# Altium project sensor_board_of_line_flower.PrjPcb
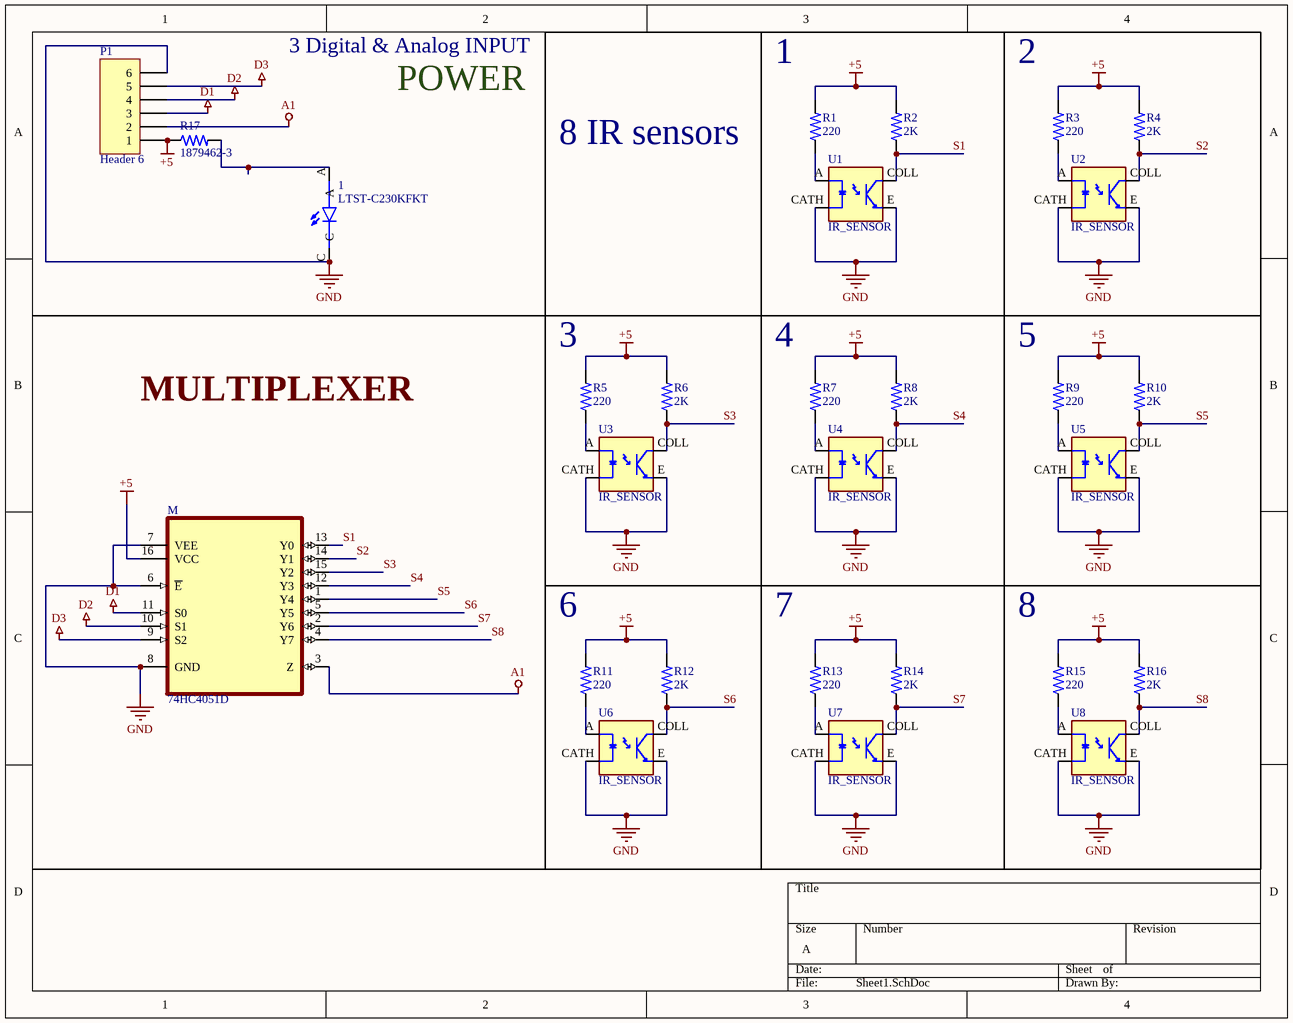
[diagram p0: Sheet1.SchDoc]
1 sheet, 28 parts. Net scope: global (net labels, ports and power ports of the same name join across sheets).
Board files: PCB1.PcbDoc, PCB2.PcbDoc, PCB3.PcbDoc

## Sheet Sheet1.SchDoc
size A; SheetNumber: 1; SheetTotal: 1

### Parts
1  LTST-C230KFKT  [LEDC3216X110]
M  74HC4051D  [SOIC127P600X175-16N]
P1  Header 6  [HDR1X6]
R1  220  [RESC3115X65N]
R2  2K  [RESC3115X65N]
R3  220  [RESC3115X65N]
R4  2K  [RESC3115X65N]
R5  220  [RESC3115X65N]
R6  2K  [RESC3115X65N]
R7  220  [RESC3115X65N]
R8  2K  [RESC3115X65N]
R9  220  [RESC3115X65N]
R10  2K  [RESC3115X65N]
R11  220  [RESC3115X65N]
R12  2K  [RESC3115X65N]
R13  220  [RESC3115X65N]
R14  2K  [RESC3115X65N]
R15  220  [RESC3115X65N]
R16  2K  [RESC3115X65N]
R17  1879462-3  [RESC3115X65N]
U1  IR_SENSOR  [OPTO_TCRT5000]
U2  IR_SENSOR  [OPTO_TCRT5000]
U3  IR_SENSOR  [OPTO_TCRT5000]
U4  IR_SENSOR  [OPTO_TCRT5000]
U5  IR_SENSOR  [OPTO_TCRT5000]
U6  IR_SENSOR  [OPTO_TCRT5000]
U7  IR_SENSOR  [OPTO_TCRT5000]
U8  IR_SENSOR  [OPTO_TCRT5000]

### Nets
+5: M.16(VCC) P1.1 R1.2 R2.2 R3.2 R4.2 R5.2 R6.2 R7.2 R8.2 R9.2 R10.2 R11.2 R12.2 R13.2 R14.2 R15.2 R16.2 R17.1
A1: M.3(Z) P1.2
D1: M.11(S0) P1.3
D2: M.10(S1) P1.4
D3: M.9(S2) P1.5
GND: 1.C M.6(~{E}) M.7(VEE) M.8(GND) P1.6 U1.CATH U1.E U2.CATH U2.E U3.CATH U3.E U4.CATH U4.E U5.CATH U5.E U6.CATH U6.E U7.CATH U7.E U8.CATH U8.E
S1: M.13(Y0) R2.1 U1.COLL
S2: M.14(Y1) R4.1 U2.COLL
S3: M.15(Y2) R6.1 U3.COLL
S4: M.12(Y3) R8.1 U4.COLL
S5: M.1(Y4) R10.1 U5.COLL
S6: M.5(Y5) R12.1 U6.COLL
S7: M.2(Y6) R14.1 U7.COLL
S8: M.4(Y7) R16.1 U8.COLL
Net1_A: 1.A R17.2
NetR1_1: R1.1 U1.A
NetR3_1: R3.1 U2.A
NetR5_1: R5.1 U3.A
NetR7_1: R7.1 U4.A
NetR9_1: R9.1 U5.A
NetR11_1: R11.1 U6.A
NetR13_1: R13.1 U7.A
NetR15_1: R15.1 U8.A

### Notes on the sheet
- 3 Digital & Analog INPUT
- POWER
- (near R1) 1
- (near R3) 2
- 8 IR sensors
- (near R5) 3
- (near R7) 4
- (near R9) 5
- MULTIPLEXER
- (near R11) 6
- (near R13) 7
- (near R15) 8

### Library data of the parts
1 = LTST-C230KFKT: Orange 605nm LED Indication - Discrete 2V 1206 (3216 Metric); MF: Lite-On Inc.
M = 74HC4051D: 1 Circuit IC Switch 8:1 130Ohm 16-SOIC; MF: Toshiba
P1 = Header 6: Header, 6-Pin
R1-R17 = 1879462-3: RL73H 2B R12 1% 5K RL
U1-U8 = TCRT5000: 950 nm 60 mA Through Hole Reflective Optical Sensor with Transistor Output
